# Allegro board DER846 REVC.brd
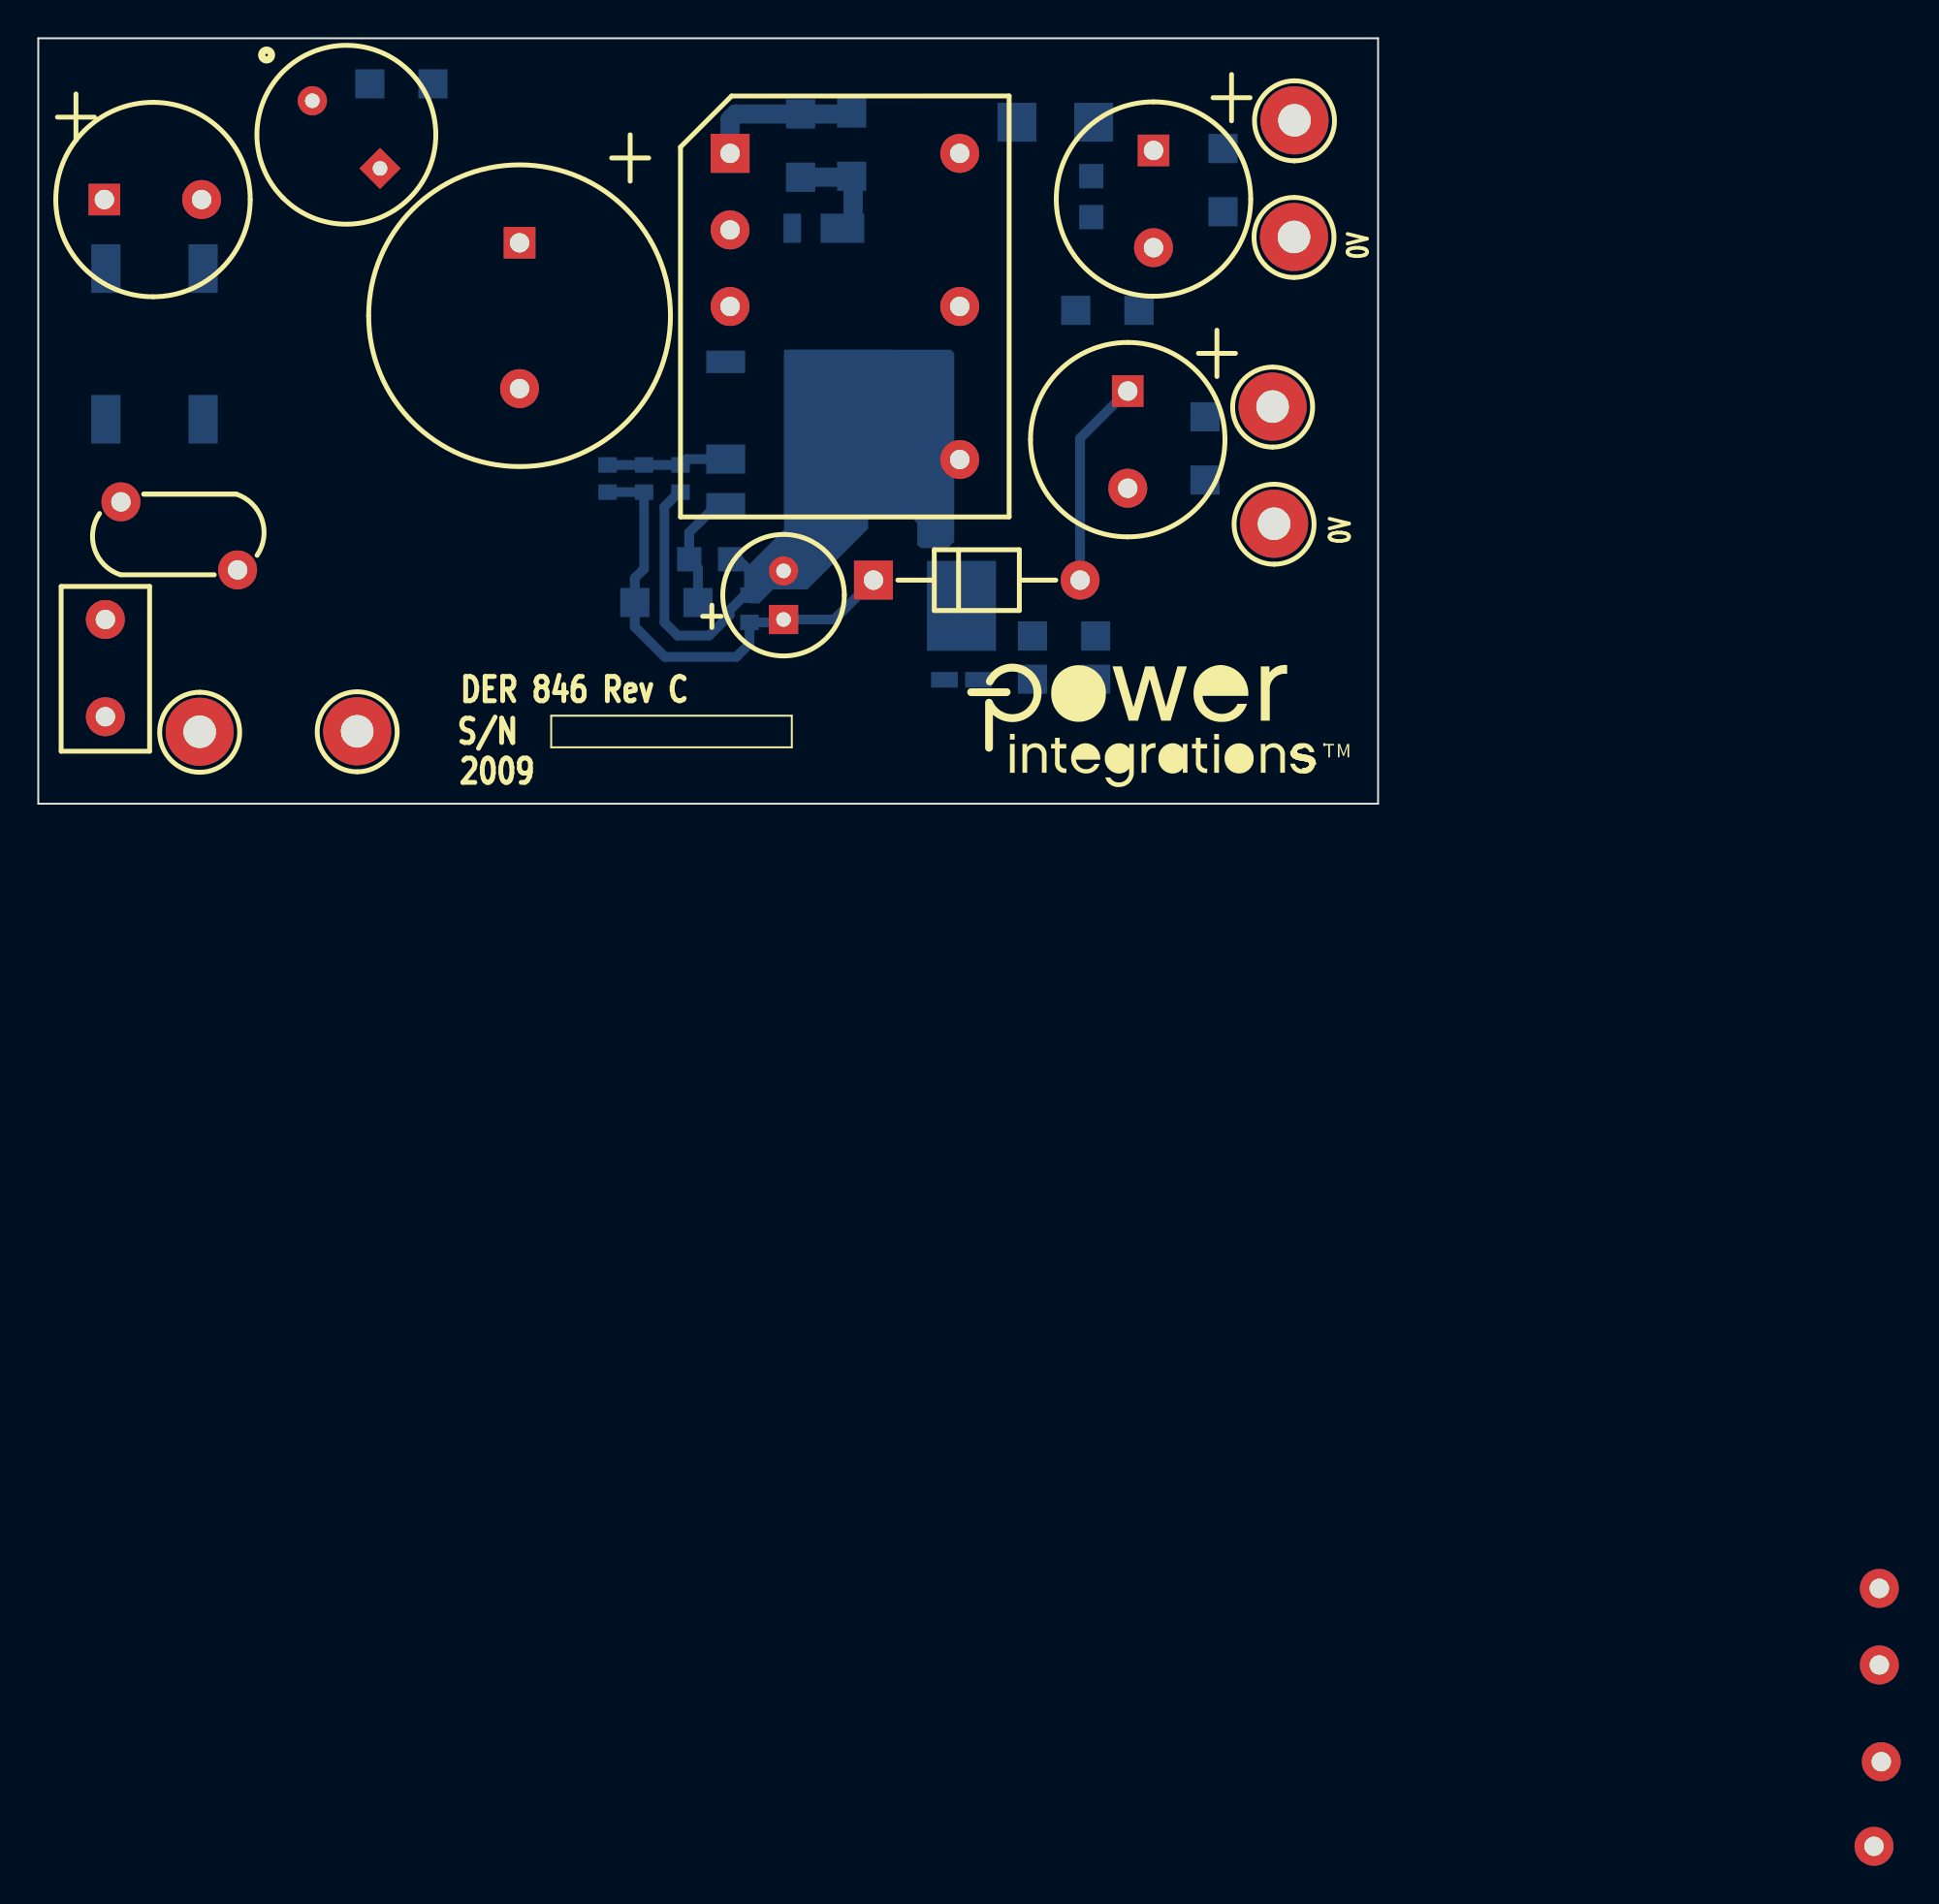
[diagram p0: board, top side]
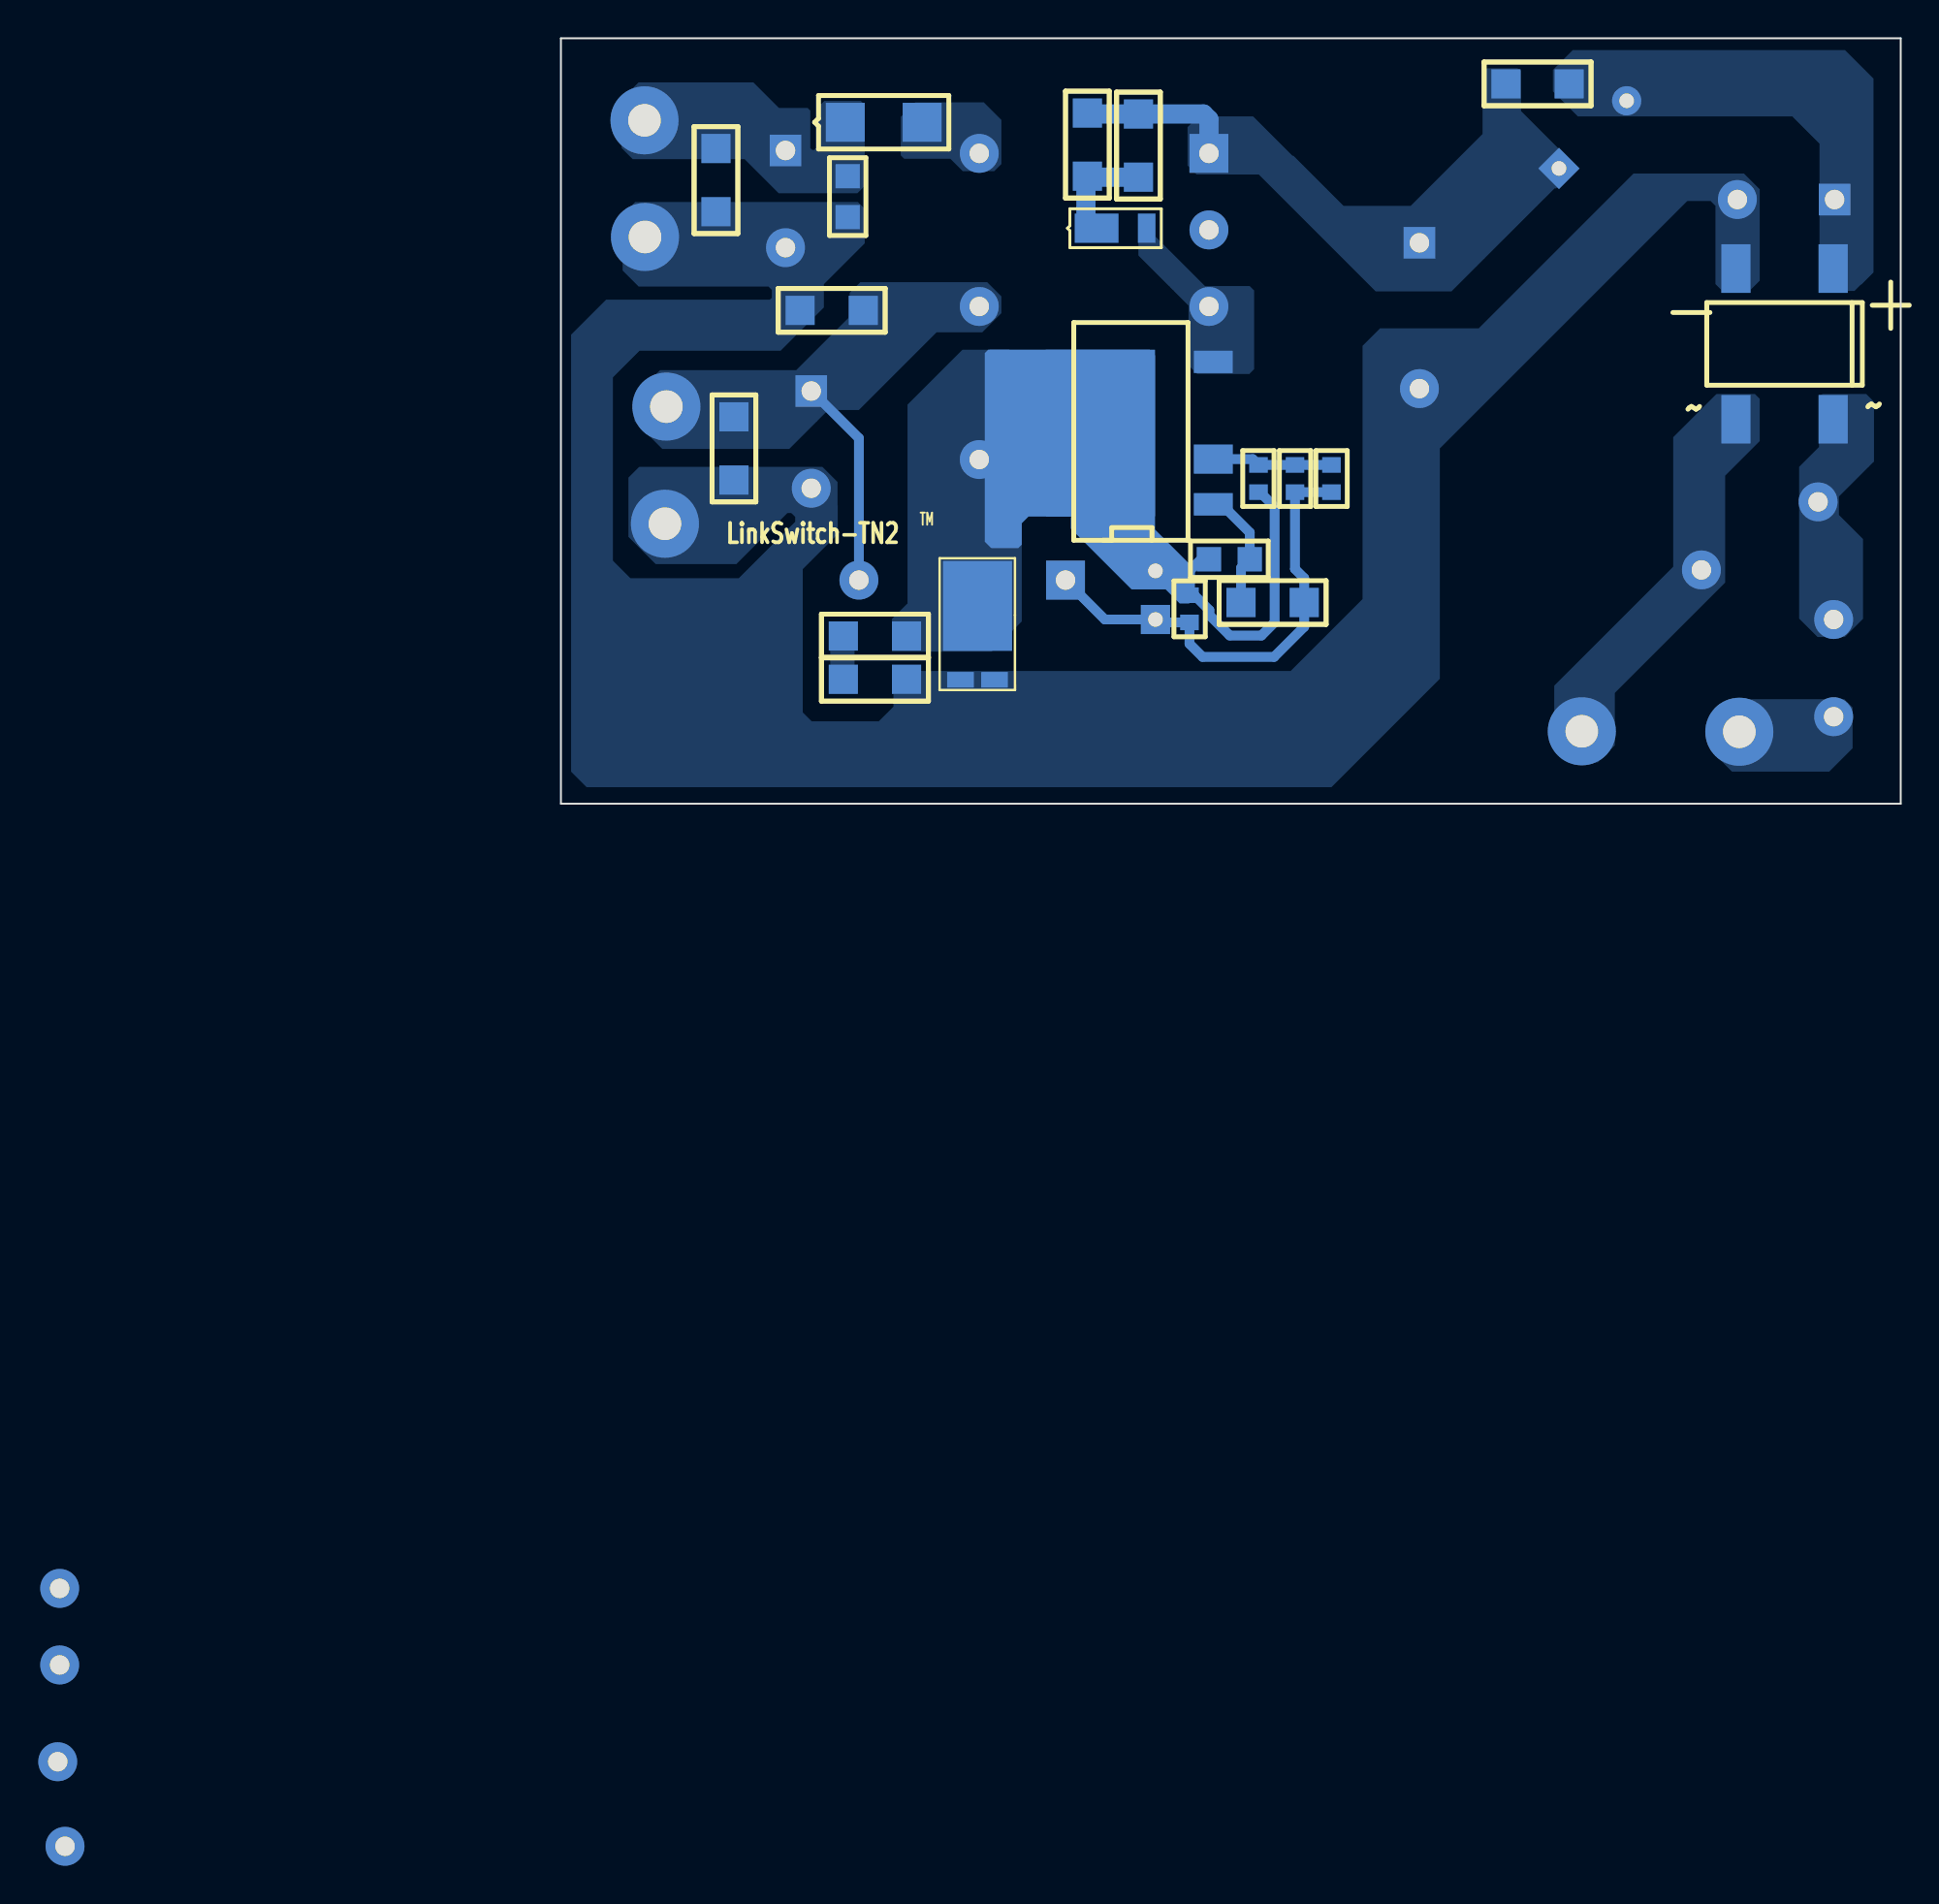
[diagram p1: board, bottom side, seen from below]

Outline 70 x 40 mm; copper layers: TOP, BOTTOM. Coordinates in mm from the lower left corner of the outline.
Outline path: 0,40 0,0 70,0 70,40 0,40

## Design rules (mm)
constraint set DEFAULT: min track width 0.508

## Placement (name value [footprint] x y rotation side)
0V  BLK  [PITPKEYSTONE125X125]  64.57 14.63 0 top
0V1  BLK  [PITPKEYSTONE125X125]  65.61 29.62 0 top
BR1  DF08S  [PISMDDFS]  3.53 27.91 180 bottom
C1  22 uF  [PIPOLCAPCYLD400LS200040]  3.45 31.57 0 top
C2  100 uF  [PIPOLCAPCYLD250LS100030]  38.94 9.63 90 top
C3  0.1 uF  [PISMC0805]  34.01 12.78 0 bottom
C4  1000 pF  [PISMC1206]  39.83 36.04 270 bottom
C6  1 nF  [PISMC1206]  51.94 8.76 0 bottom
C7  0.1 uF  [PISMC0603]  29.74 16.28 90 bottom
C8  330 uF  [PIPOLCAPCYLD400LS200040]  58.27 34.14 270 top
C9  33 uF  [PIPOLCAPCLYD630LS300040]  25.15 29.31 270 top
C10  0.1 uF  [PISMC0603]  37.16 9.47 90 bottom
C11  680 uF  [PIPOLCAPCYLD400LS200040]  56.92 21.56 270 top
C12  0.47 uF  [PISMC0805]  55.02 32.79 270 bottom
C13  10 uF  [PISMC1206]  54.2 25.78 0 bottom
D1  DFLR1800-7  [PISMDDFLR120012]  42.04 30.07 0 bottom
D2  1N4935-T  [PIDV200X110X040DO41]  43.64 11.68 0 top
D3  US1M-13-F  [PISMDSMA]  55.14 35.61 180 bottom
D4  SDT5H100P5-7  [PISMDPOWERDI5]  49.12 6.48 180 bottom
F1  1 A  [PI_RST_MICROFUSE]  3.51 4.55 90 top
L  WHT  [PITPKEYSTONE125X125]  8.43 3.76 0 top
L1  1.5 mH  [PI_CHOKE_RLB9012_D2]  17.86 33.2 135 top
N  BLK  [PITPKEYSTONE125X125]  16.66 3.78 0 top
NOREF  -  []  48.54 7.29 0 top
NOREF#2  -  []  -228.6 -144.78 0 top
NOREF#3  -  []  70 0 90 top
NOREF#4  -  []  0 40 0 top
NOREF#5  -  []  -150.78 54.23 0 top
R2  2.4 K  [PISMR0603]  33.55 17.7 270 bottom
R3  11 k  [PISMR0603]  31.65 16.28 90 bottom
R5  39  [PISMR1206]  55.24 6.5 180 bottom
R6  4.3 k  [PISMR1206]  61.9 34.24 270 bottom
R8  8.25 k  [PISMR1206]  31.17 10.52 0 bottom
R9  470  [PISMR1206]  17.32 37.62 0 bottom
R10  100 k  [PISMR1206]  42.49 36.09 270 bottom
R11  4.75 k  [PISMR1206]  60.96 20.22 270 bottom
RV1  275 Vac  [PIDISC350X160LS210X140040]  4.32 15.77 0 top
T1  EE22  [PIBOBBINEE22V10PTDK]  36.14 33.99 0 top
U1  LNK3206G  [PIICSMD8CSHORT5678]  35.92 15.65 90 bottom
UNK+12V  RED  [PITPKEYSTONE125X125]  64.49 20.75 0 top
UNK+15V  BLU  [PITPKEYSTONE125X125]  65.63 35.71 0 top

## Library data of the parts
0V 0V1 L N UNK+12V UNK+15V = TESTPOINT
BR1 = DIODE BRIDGE_+-~~
C1 = CAP POL: alternate symbols: (pipolcapclyd12p5x20ls5d40h)
C2 = CAP POL: alternate symbols: (pipolcapcyld250ls100030h)
C3 C4 C6 C7 C10 C12 C13 = CAP NP
C8 = CAP POL: alternate symbols: (pipolcapclyd395x630ls200030h)
C9 = CAP POL: alternate symbols: (pipolcapclyd630ls300040800h)
C11 = CAP POL: alternate symbols: (pipolcapclyd10d14h030H)
D1 D3 = DIODE
D2 = DIODE: alternate symbols: (pidax475x125040do41,pidv200x110x040do41wbead,pidax390x125040do41)
D4 = DS_DUAL_CK_A_AC
F1 = FUSE: alternate symbols: (pirstmicrofusehoz)
L1 = INDUCTOR_DOT2
R2 R3 R5 R6 R8-R11 = R
RV1 = VARISTOR: alternate symbols: (pi_disc_354x220_ls220x10_040_h)
T1 = BEEL22_10P/GENERIC
U1 = LNK32XX_8C

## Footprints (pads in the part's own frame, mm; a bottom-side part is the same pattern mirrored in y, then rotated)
PI_CHOKE_RLB9012_D2
  rect 1.524x1.524 hole 0.762: 1(0,0)
  round 1.524 hole 0.762: 2(5.001,0)
PI_RST_MICROFUSE
  round 2.032 hole 1.016: 1(0,0) 2(5.08,0)
PIBOBBINEE22V10PTDK
  rect 2.032x2.032 hole 1.016: 1(0,0)
  round 2.032 hole 1.016: 2(0,-4) 3(0,-8.001) 4(60.046,-74.991) 5(60.046,-78.992) 6(11.999,-16) 7(59.766,-88.468) 8(11.999,-8.001) 9(60.147,-84.049) 10(11.999,0)
PIDISC350X160LS210X140040
  round 2.032 hole 1.016: 1(0,0) 2(6.096,-3.556)
PIDV200X110X040DO41
  rect 2.032x2.032 hole 1.016: 1(0,0)
  round 2.032 hole 1.016: 2(10.795,0)
PIICSMD8CSHORT5678
  rect 1.168x2.032 smd: 1(0,0) 4(7.442,0) 5(7.442,8.636) 8(0,8.636)
  rect 1.524x2.032 smd: 2(2.362,0) 6(4.902,8.636) 7(2.362,8.636)
PIPOLCAPCLYD630LS300040
  rect 1.651x1.651 hole 1.016: 1(0,0)
  round 2.032 hole 1.016: 2(7.62,0)
PIPOLCAPCYLD250LS100030
  rect 1.524x1.524 hole 0.762: 1(0,0)
  round 1.524 hole 0.762: 2(2.54,0)
PIPOLCAPCYLD400LS200040
  rect 1.651x1.651 hole 1.016: 1(0,0)
  round 2.032 hole 1.016: 2(5.08,0)
PISMC0603
  rect 0.813x0.965 smd: 1(0,0) 2(1.422,0)
PISMC0805
  rect 1.27x1.27 smd: 1(0,0) 2(2.134,0)
PISMC1206
  rect 1.524x1.524 smd: 1(0,0) 2(3.302,0)
PISMDDFLR120012
  rect 2.286x1.524 smd: 1(-0.025,0)
  rect 0.914x1.524 smd: 2(-2.642,0)
PISMDDFS
  rect 1.524x2.54 smd: 1(0,0.051) 2(-5.08,0.051) 3(0,-7.823) 4(-5.08,-7.823)
PISMDPOWERDI5
  rect 1.397x0.813 smd: 1(0,0) 3(1.778,0)
  rect 3.607x4.699 smd: 2(0.889,3.861)
PISMDSMA
  rect 2.032x2.032 smd: 1(0,0) 2(4.013,0)
PISMR0603
  rect 0.813x0.965 smd: 1(0,0) 2(1.422,0)
PISMR1206
  rect 1.524x1.524 smd: 1(0,0) 2(3.302,0)
PITPKEYSTONE125X125
  round 3.556 hole 1.702: 1(0,0)

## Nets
SOURCE: U1.6 U1.7 U1.8
N00464: BR1.1 C1.1 L1.2 R9.1
N01028: C4.1 C9.1 L1.1 R9.2 R10.1 T1.1
N02503: BR1.3 F1.2 RV1.1
N04889: D1.2 T1.3 U1.4
N05128: C3.1 R8.2 U1.1
N05532: C2.2 C3.2 C6.1 C10.2 D4.2(K) R2.2 T1.6 U1.5(S)
N05805: C2.1 C7.1 C10.1 D2.1 R3.1 R8.1
N06465: C7.2 R2.1 R3.2 U1.2
N09220: 0V.1 0V1.1 BR1.2 C1.2 C8.2 C9.2 C11.2 C12.2 C13.2 D4.1 D4.3 R5.2 R6.2 R11.2
N11458: C4.2 D1.1 R10.2
N14333: F1.1 L.1
N14338: BR1.4 N.1 RV1.2
N20013: C11.1 C13.1 D2.2 R11.1 T1.8 UNK+12V.1
N47720: C8.1 C12.1 D3.1 R6.1 UNK+15V.1
N56683: D3.2 T1.10
N60111: C6.2 R5.1

Pads without a net: T1 2 4 5 7 9

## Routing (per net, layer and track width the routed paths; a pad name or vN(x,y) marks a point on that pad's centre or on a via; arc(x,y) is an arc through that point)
N01028: length 8.3
  BOTTOM w1: R10.1 42.44,36.04 C4.1 36.43,36.04 36.14,35.76 T1.1
N05128: length 6.4
  BOTTOM w0.508: U1.1 35.48,15.65 34.01,14.17 C3.1 34.47,12.32 R8.2
N05532: length 17.8
  BOTTOM w0.508: C10.2 37.13,10.87 ; C10.2 36.9,10.9 36.12,10.11 36.12,9.85 35.05,8.79 33.4,8.79 32.71,9.48 32.71,15.52 33.48,16.28 R2.2 ; C10.2 37.16,12.17 36.58,12.75 36.3,12.75 36.27,12.78 C3.2 ; C10.2 37.67,10.9 C2.2
N05805: length 24.6
  BOTTOM w0.508: D2.1 41.58,9.63 C2.1 38.79,9.47 C10.1 37.16,8.36 36.47,7.67 32.74,7.67 31.17,9.25 R8.1 31.17,11.79 31.65,12.27 R3.1 C7.1
N06465: length 6.3
  BOTTOM w0.508: C7.2 R3.2 R2.1 33.86,18.01 U1.2
N11458: length 5.7
  BOTTOM w1: D1.1 42.57,30.63 42.57,32.72 R10.2 42.44,32.74 C4.2
N20013: length 11
  BOTTOM w0.508: D2.2 54.43,19.1 56.92,21.59 C11.1

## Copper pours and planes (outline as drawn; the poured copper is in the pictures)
N00464 on BOTTOM: 2.41,26.8 2.08,27.13 2.06,27.13 1.42,27.76 1.42,37.9 2.91,39.38 17.13,39.38 18.17,38.34 18.17,37.22 16.87,35.92 5.66,35.92 4.24,34.49 4.24,26.8
N01028 on BOTTOM: 18.08,32.16 18.01,32.16 17.4,32.77 17.4,33.76 19.84,36.2 19.84,38.28 19.94,38.38 19.96,38.38 20.02,38.43 21.67,38.43 21.84,38.25 21.84,35 25.6,31.24 29.11,31.24 31.72,33.86 31.78,33.86 33.83,35.92 36.7,35.92 37.26,35.36 37.26,33.35 36.79,32.88 33.54,32.88 27.43,26.77 23.47,26.77
N02503 on BOTTOM: 4.09,21.41 1.8,21.41 1.4,21.01 1.4,17.88 3.23,16.05 3.23,15.09 1.97,13.83 1.97,9.66 2.92,8.71 4.34,8.71 5.31,9.68 5.31,17.6 4.27,18.64 4.27,21.23
N04889 on BOTTOM: 37.21,22.91 37.21,26.04 39.83,28.65 39.83,30.73 39.75,30.81 39.07,30.81 38.94,30.68 38.94,29.64 36.35,27.05 34.01,27.05 33.78,26.82 33.78,22.71 34.04,22.45 36.75,22.45
N05532 on BOTTOM (solid shape): 44.68,15.01 38.96,15.01 38.96,23.72 44.68,23.72
N05532 on BOTTOM (solid shape): 47.85,23.55 47.85,13.69 47.52,13.36 46.1,13.36 45.92,13.54 45.92,14.66 45.57,15.01 43.31,15.01 43.36,14.96 43.36,14.38 40.18,11.2 38.4,11.2 37.67,10.46 37.19,10.46 36.88,10.77 36.88,12.24 38.96,14.33 38.96,23.44 39.24,23.72 47.68,23.72
N05532 on BOTTOM: 46.58,23.75 47.6,23.75 47.62,23.72 49.02,23.72 51.89,20.85 51.89,10.46 52.7,9.65 52.7,7.95 47.5,7.95 45.92,9.53 45.92,14.05 46.56,14.68 46.56,23.72
N09220 on BOTTOM: 29.74,0.86 24.08,6.53 24.08,18.57 11.15,31.5 9.93,31.5 9.68,31.24 9.68,27.15 9.3,26.77 7.92,26.77 7.37,27.33 7.37,32.11 8.19,32.93 13.96,32.93 22.05,24.84 27.2,24.84 28.12,23.93 28.12,10.69 31.88,6.93 52.22,6.93 52.63,6.53 52.63,5.07 53.39,4.31 56.9,4.31 57.37,4.78 57.37,12.26 55.54,14.08 55.54,15.58 55.55,15.6 55.55,16.81 56.34,17.6 65.91,17.6 66.47,17.04 66.47,13.94 65.05,12.52 60.83,12.52 58.17,15.19 57.96,15.19 57.76,14.99 57.76,14.73 60.71,11.79 66.37,11.79 67.28,12.7 67.28,22.28 65.89,23.67 58.52,23.67 56.26,25.93 56.26,27.15 54.13,29.29 54.13,31.09 54.48,31.45 66.12,31.45 66.78,30.78 66.78,27.86 65.94,27.03 59.16,27.03 58.98,26.85 58.98,26.44 59.08,26.34 67.64,26.34 69.47,24.51 69.47,1.68 68.66,0.86
N14333 on BOTTOM: 8.81,1.68 3.73,1.68 2.51,2.9 2.51,5.03 2.95,5.46 8.97,5.46 9.96,4.47 9.96,2.82
N14338 on BOTTOM: 9.17,17.14 7.37,18.95 7.37,21.16 7.62,21.41 9.63,21.41 11.89,19.15 11.89,12.38 18.1,6.17 18.1,2.86 17.4,2.16 15.82,2.16 14.94,3.05 14.94,5.79 9.17,11.56
N20013 on BOTTOM: 58.06,18.54 56.03,20.57 54.43,20.57 50.37,24.64 47.98,24.64 46.99,25.63 46.99,26.52 47.73,27.25 54.36,27.25 54.91,26.7 54.91,25.45 57.71,22.66 64.82,22.66 66.15,21.32 66.15,19.99 64.71,18.54
N47720 on BOTTOM: 58.62,31.9 60.4,33.68 66.24,33.68 66.83,34.26 66.83,36.8 65.94,37.69 59.94,37.69 58.61,36.36 57.11,36.36 56.97,36.22 56.97,34.26 56.87,34.16 56.77,34.16 56.67,34.26 56.67,36.31 56.62,36.36 56.6,36.36 56.24,36.73 54.33,36.73 54.13,36.53 54.13,32.28 54.51,31.9
N56683 on BOTTOM: 47.36,33.06 49.01,33.06 49.66,33.71 52.07,33.71 52.25,33.88 52.25,35.89 51.49,36.65 47.9,36.65 46.99,35.74 46.99,33.43
N60111 on BOTTOM: 54.66,8.94 54.66,6.76 55.19,6.22 55.83,6.22 55.93,6.32 55.93,8.79 55.47,9.25 54.97,9.25

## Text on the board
Ref Des/Silkscreen Bottom: TM | LinkSwitch-TN2
Ref Des/Silkscreen Top: 0V | S/N | 2009 | DER 846 Rev C
User.6: 14.  FAB HOUSE LOGO,DATE CODE TO BE IN SILK SCREEN ONLY.DO NOT USE COPPER. | 13.  MATERIAL FR4 COPPER 2oz THICKNESS 0.062"
